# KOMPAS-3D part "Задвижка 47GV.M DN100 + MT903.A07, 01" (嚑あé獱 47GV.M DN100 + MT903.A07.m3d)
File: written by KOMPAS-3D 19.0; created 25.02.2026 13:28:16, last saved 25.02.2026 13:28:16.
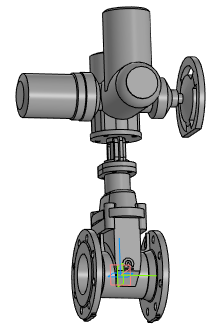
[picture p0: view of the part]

Document properties: Автор: Энергия; Полное имя файла: 47GV.M DN100\Задвижка 47GV.M DN100 с переходом под ISO фланец.a3d

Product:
- Part/product: Задвижка 47GV.M DN100 + MT903.A07  | designation 01
    Масса: 15.8677
  - Component [detail]: Удлинитель шпинделя  | Материал: Сталь 20Х13 ГОСТ 5632-72 (density 7670 kg/m3); Масса: 0.393756; source file: 47GV.M DN80\DR.47GVAM.100.16.00.002 - Удлинитель шпинделя.cdw, 47GV.M DN80\Удлинитель шпинделя DN100.m3d
  - Component [detail]: Стойка  | Материал: ВЧ50 ГОСТ 7293-85 (density 7200 kg/m3); Масса: 1.9123; source file: 47GV.M DN80\DR.47GVAM.100.16.00.001 - Стойка.cdw, 47GV.M DN80\Стойка DN100.m3d
  - Component [detail]: Шпиндель  | pos. 5  | Материал: Сталь 20Х13 ГОСТ 5632 - 2014 (density 7670 kg/m3); Масса: 0.114456; Раздел спецификации: Детали; Форматы листов документа: A3; source file: 47GV.M DN80\DR.47GVM.080.16.00.003 - Шпиндель.cdw, 47GV.M DN80\Шпиндель DN80.m3d
  - Component [assembly]: Клин с направляющими  | designation DR.47GVM.080.16.01.000  | pos. 4  | Раздел спецификации: Сборочные единицы; Форматы листов документа: A4; source file: 47GV.M DN100\DR.47GVM.080.16.01.000 - Клин с направляющими.a3d, 47GV.M DN100\DR.47GVM.080.16.01.000 - Клин с направляющими.spw, 47GV.M DN100\DR.47GVM.080.16.01.000 СБ - Клин с направляющими.cdw
  - Component [detail]: Корпус DN100  | pos. 3  | Материал: ВЧ50 ГОСТ 7293-85 (density 7200 kg/m3); Масса: 19.2555; Раздел спецификации: Детали; Форматы листов документа: 2xA3; source file: 47GV.M DN100\DR.47GV.100.16.00.001 - Корпус.cdw, 47GV.M DN100\DR.47GVM.050.16.00.001 - Корпус.cdw, 47GV.M DN100\DR.47GVM.100.16.00.001 - Корпус.cdw, 47GV.M DN100\Корпус DN100.m3d
  - Component [detail]: Крышка DN100  | pos. 4  | Материал: ВЧ50 ГОСТ 7293-85 (density 7200 kg/m3); Масса: 6.92658; Раздел спецификации: Детали; Форматы листов документа: 2xA3; source file: 47GV.M DN100\DR.47GVM.100.16.00.002 - Крышка.cdw, 47GV.M DN100\Крышка DN100.m3d
  - Component: Электропривод МТ903.А07 без блока управления  | Масса: 65.4738; source file: 47GV.M DN50\Электропривод МТ903.А07 без блока управления.m3d
- Part/product: Задвижка 47GV.M DN100 + MT903.A07
    Масса: 94.0764
  - Component: Задвижка с обрезиненным клином DN80. Сборочный чертеж  | designation DR.47GVM.080.16.00.00СБ  | pos. 0  | Масса: 15.8764; Раздел спецификации: Документация; Форматы листов документа: 2xA3; source file: 47GV.M DN100\DR.47GVM.080.16.00.000 СБ - Задвижка с обрезиненным клином DN80.cdw

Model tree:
1. Операция без истории:1

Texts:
  Точка начала. Х
  Точка начала. Y
  Точка начала. Z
